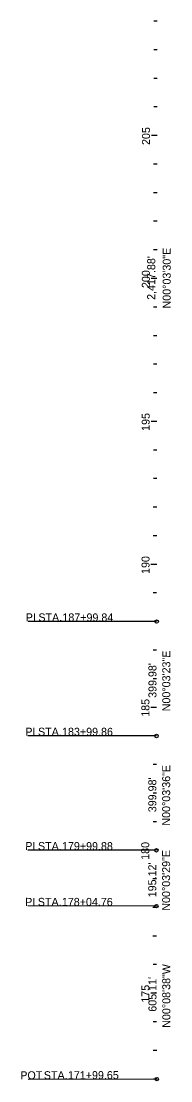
# Model space of a CAD drawing. Extents: x 1807668 to 1809726, y 297763 to 325145.
# Drawn here: x 1808191 to 1808715, y 297763 to 301469 of the extents above; entities that cross this region are included whole.
import ezdxf

# ---------------------------------------------------------------- set-up
doc = ezdxf.new("R2010")
doc.units = 0
for name, color, linetype in [('GE_P_Alignment_500_Bearings', 7, 'Continuous'), ('GE_P_Alignment_500_Cardinal_Points', 7, 'Continuous'), ('GE_P_Alignment_500_Distances', 7, 'Continuous'), ('GE_P_Alignment_500_Stations', 7, 'Continuous')]:
    doc.layers.add(name, color=color, linetype=linetype)

msp = doc.modelspace()

# ---------------------------------------------------------------- linework, layer by layer
at = {"layer": 'GE_P_Alignment_500_Cardinal_Points'}
for p, q in [((1808665.1, 299369.1), (1808215.1, 299369.5)), ((1808664.7, 298969.1), (1808214.7, 298969.5)), ((1808664.3, 298569.1), (1808214.3, 298569.6)), ((1808664.1, 298374), (1808214.1, 298374.4)), ((1808665.6, 297768.9), (1808215.6, 297767.8))]:
    msp.add_line(p, q, dxfattribs=at)
for centre in [(1808665.1, 299369.1), (1808664.7, 298969.1), (1808664.3, 298569.1), (1808664.1, 298374), (1808665.6, 297768.9)]:
    msp.add_circle(centre, 6, dxfattribs=at)
at = {"layer": 'GE_P_Alignment_500_Stations'}
for p, q in [((1808667.2, 301469.2), (1808655.2, 301469.2)), ((1808667.1, 301369.2), (1808655.1, 301369.2)), ((1808667, 301269.2), (1808655, 301269.2)), ((1808666.9, 301169.2), (1808654.9, 301169.2)), ((1808666.8, 301069.2), (1808646.8, 301069.2)), ((1808666.7, 300969.2), (1808654.7, 300969.2)), ((1808666.6, 300869.2), (1808654.6, 300869.2)), ((1808666.5, 300769.2), (1808654.5, 300769.2)), ((1808666.4, 300669.2), (1808654.4, 300669.2)), ((1808666.3, 300569.2), (1808646.3, 300569.2)), ((1808666.2, 300469.2), (1808654.2, 300469.2)), ((1808666.1, 300369.2), (1808654.1, 300369.2)), ((1808666, 300269.2), (1808654, 300269.2)), ((1808665.9, 300169.2), (1808653.9, 300169.2)), ((1808665.8, 300069.2), (1808645.8, 300069.2)), ((1808665.7, 299969.2), (1808653.7, 299969.2)), ((1808665.6, 299869.2), (1808653.6, 299869.2)), ((1808665.5, 299769.2), (1808653.5, 299769.2)), ((1808665.4, 299669.2), (1808653.4, 299669.2)), ((1808665.3, 299569.2), (1808645.3, 299569.2)), ((1808665.2, 299469.2), (1808653.2, 299469.2)), ((1808665.1, 299369.2), (1808653.1, 299369.2)), ((1808665, 299269.2), (1808653, 299269.2)), ((1808664.9, 299169.2), (1808652.9, 299169.2)), ((1808664.8, 299069.2), (1808644.8, 299069.2)), ((1808664.7, 298969.2), (1808652.7, 298969.2)), ((1808664.6, 298869.2), (1808652.6, 298869.2)), ((1808664.5, 298769.2), (1808652.5, 298769.2)), ((1808664.4, 298669.2), (1808652.4, 298669.2)), ((1808664.3, 298569.2), (1808644.3, 298569.2)), ((1808664.2, 298469.2), (1808652.2, 298469.2)), ((1808664.1, 298369.2), (1808652.1, 298369.2)), ((1808664.3, 298269.2), (1808652.3, 298269.2)), ((1808664.6, 298169.2), (1808652.6, 298169.2)), ((1808664.8, 298069.2), (1808644.8, 298069.2)), ((1808665.1, 297969.2), (1808653.1, 297969.2)), ((1808665.3, 297869.2), (1808653.3, 297869.2)), ((1808665.6, 297769.2), (1808653.6, 297769.2))]:
    msp.add_line(p, q, dxfattribs=at)

# ---------------------------------------------------------------- texts
at = {"layer": 'GE_P_Alignment_500_Bearings'}
for s, rotation, p in [('N00°03\'30"E', 89.9418, (1808714.2, 300464.3)), ('N00°03\'23"E', 89.9436, (1808712.8, 299055.4)), ('N00°03\'36"E', 89.94, (1808712.4, 298655.4)), ('N00°03\'29"E', 89.9419, (1808712.1, 298357.9)), ('N00°08\'38"W', 90.1438, (1808713.1, 297948.4))]:
    msp.add_text(s, height=28, rotation=rotation, dxfattribs=at).set_placement(p)
at = {"layer": 'GE_P_Alignment_500_Cardinal_Points'}
for s, rotation, p in [('PI', 359.9418, (1808206.9, 299370)), (' STA. ', 359.9418, (1808240.8, 299369.9)), ('187+99.84', 359.9418, (1808335.3, 299369.8)), ('PI', 359.9436, (1808205.6, 298970)), (' STA. ', 359.9436, (1808239.5, 298969.9)), ('183+99.86', 359.9436, (1808334.1, 298969.8)), ('PI', 359.94, (1808205.4, 298570)), (' STA. ', 359.94, (1808239.4, 298570)), ('179+99.88', 359.94, (1808333.9, 298569.9)), ('PI', 359.9419, (1808205, 298374.9)), (' STA. ', 359.9419, (1808238.9, 298374.8)), ('178+04.76', 359.9419, (1808333.4, 298374.7)), ('POT', 0.1438, (1808188, 297768.1)), (' STA. ', 0.1438, (1808260, 297768.3)), ('171+99.65', 0.1438, (1808354.6, 297768.5))]:
    msp.add_text(s, height=28, rotation=rotation, dxfattribs=at).set_placement(p)
at = {"layer": 'GE_P_Alignment_500_Distances'}
for s, rotation, p in [("2,417.88'", 89.9418, (1808660, 300494.5)), ("399.98'", 89.9436, (1808664.4, 299102.3)), ("399.98'", 89.94, (1808664, 298702.3)), ("195.12'", 89.9419, (1808663.7, 298404.8)), ("605.11'", 90.1438, (1808664.6, 298004.6))]:
    msp.add_text(s, height=28, rotation=rotation, dxfattribs=at).set_placement(p)
at = {"layer": 'GE_P_Alignment_500_Stations'}
for s, rotation, p in [('205', 89.9418, (1808641.8, 301036.2)), ('200', 89.9418, (1808641.3, 300535.8)), ('195', 89.9418, (1808640.8, 300036.2)), ('190', 89.9418, (1808640.3, 299535.8)), ('185', 89.9436, (1808639.8, 299036.2)), ('180', 89.94, (1808639.2, 298535.8)), ('175', 90.1438, (1808639.9, 298036.1))]:
    msp.add_text(s, height=28, rotation=rotation, dxfattribs=at).set_placement(p)

doc.saveas('drawing.dxf')
